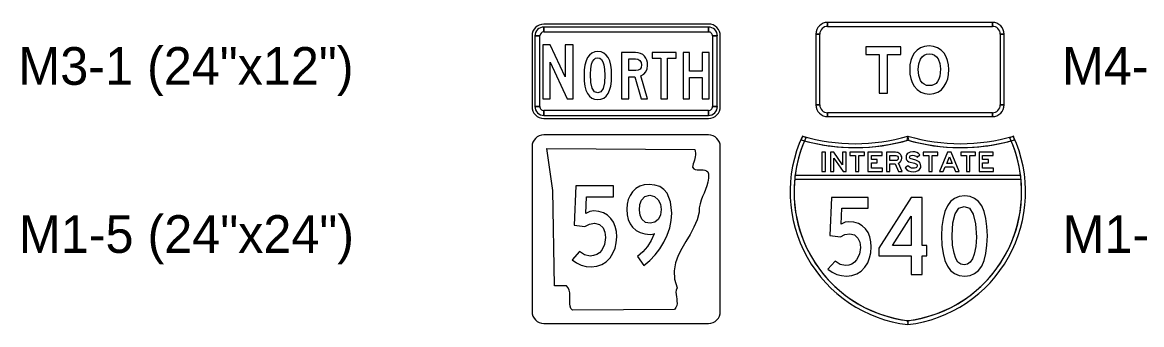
# Model space of a CAD drawing. Extents: x 620856.8 to 620948.6, y 415598.8 to 415658.2.
# Drawn here: x 620875.52 to 620887.41, y 415642.91 to 415646.11 of the extents above; entities that cross this region are included whole.
import ezdxf

# ---------------------------------------------------------------- set-up
doc = ezdxf.new("R2010")
doc.units = 0
doc.layers.add('SIGNS', color=7, linetype='Continuous')

msp = doc.modelspace()

# ---------------------------------------------------------------- linework, layer by layer
at = {"layer": 'SIGNS'}
for p, q in [((620882.81, 415646.094), (620881.06, 415646.094)), ((620881.06, 415646.011), (620881.06, 415646.063)), ((620882.81, 415646.063), (620882.81, 415646.011)), ((620885.825, 415646.112), (620884.075, 415646.112)), ((620884.075, 415646.07), (620884.075, 415646.112)), ((620885.825, 415646.112), (620885.825, 415646.07)), ((620880.935, 415645.969), (620880.935, 415645.219)), ((620880.966, 415645.969), (620881.018, 415645.969)), ((620882.851, 415645.969), (620882.903, 415645.969)), ((620882.935, 415645.219), (620882.935, 415645.969)), ((620883.95, 415645.987), (620883.95, 415645.237)), ((620883.95, 415645.987), (620883.991, 415645.987)), ((620885.908, 415645.987), (620885.95, 415645.987)), ((620885.95, 415645.237), (620885.95, 415645.987)), ((620884.852, 415645.852), (620884.481, 415645.852)), ((620884.481, 415645.852), (620884.481, 415645.77)), ((620884.852, 415645.77), (620884.852, 415645.852)), ((620884.481, 415645.77), (620884.622, 415645.77)), ((620884.622, 415645.77), (620884.622, 415645.362)), ((620884.709, 415645.362), (620884.709, 415645.77)), ((620884.709, 415645.77), (620884.852, 415645.77)), ((620884.622, 415645.362), (620884.709, 415645.362)), ((620881.018, 415645.219), (620880.966, 415645.219)), ((620882.903, 415645.219), (620882.851, 415645.219)), ((620883.991, 415645.237), (620883.95, 415645.237)), ((620885.95, 415645.237), (620885.908, 415645.237)), ((620881.06, 415645.125), (620881.06, 415645.177)), ((620882.81, 415645.177), (620882.81, 415645.125)), ((620884.075, 415645.112), (620884.075, 415645.154)), ((620884.075, 415645.112), (620885.825, 415645.112)), ((620885.825, 415645.154), (620885.825, 415645.112)), ((620881.06, 415645.094), (620882.81, 415645.094)), ((620882.81, 415644.918), (620881.06, 415644.918)), ((620883.807, 415644.905), (620883.795, 415644.865)), ((620883.845, 415644.888), (620883.807, 415644.905)), ((620884.927, 415644.905), (620884.915, 415644.865)), ((620884.938, 415644.865), (620884.927, 415644.905)), ((620886.047, 415644.905), (620886.009, 415644.888)), ((620886.058, 415644.865), (620886.047, 415644.905)), ((620880.935, 415644.793), (620880.935, 415643.043)), ((620882.935, 415643.043), (620882.935, 415644.793)), ((620883.725, 415644.447), (620886.128, 415644.447)), ((620886.124, 415644.489), (620883.73, 415644.489)), ((620880.935, 415643.043), (620880.935, 415643.043)), ((620881.06, 415642.918), (620882.81, 415642.918)), ((620884.922, 415642.947), (620884.927, 415642.905)), ((620884.927, 415642.905), (620884.932, 415642.947))]:
    msp.add_line(p, q, dxfattribs=at)
for points in [[(620882.81, 415646.063), (620881.06, 415646.063), (620881.06, 415646.011), (620882.81, 415646.011), (620882.81, 415646.063), (620882.81, 415646.063)], [(620885.825, 415646.112), (620884.075, 415646.112), (620884.075, 415646.07), (620885.825, 415646.07), (620885.825, 415646.112), (620885.825, 415646.112)], [(620880.966, 415645.969), (620880.966, 415645.219), (620881.018, 415645.219), (620881.018, 415645.969), (620880.966, 415645.969), (620880.966, 415645.969)], [(620882.903, 415645.219), (620882.903, 415645.969), (620882.851, 415645.969), (620882.851, 415645.219), (620882.903, 415645.219), (620882.903, 415645.219)], [(620883.95, 415645.987), (620883.95, 415645.237), (620883.991, 415645.237), (620883.991, 415645.987), (620883.95, 415645.987), (620883.95, 415645.987)], [(620885.95, 415645.237), (620885.95, 415645.987), (620885.908, 415645.987), (620885.908, 415645.237), (620885.95, 415645.237), (620885.95, 415645.237)], [(620881.05, 415645.302), (620881.129, 415645.302), (620881.129, 415645.689), (620881.309, 415645.302), (620881.373, 415645.302), (620881.373, 415645.874), (620881.286, 415645.874), (620881.286, 415645.533), (620881.129, 415645.874), (620881.05, 415645.874)], [(620884.622, 415645.362), (620884.709, 415645.362), (620884.709, 415645.77), (620884.852, 415645.77), (620884.852, 415645.852), (620884.481, 415645.852), (620884.481, 415645.77), (620884.622, 415645.77)], [(620882.302, 415645.302), (620882.373, 415645.302), (620882.373, 415645.731), (620882.465, 415645.731), (620882.465, 415645.793), (620882.212, 415645.793), (620882.212, 415645.731), (620882.302, 415645.731)], [(620882.539, 415645.302), (620882.607, 415645.302), (620882.607, 415645.527), (620882.741, 415645.527), (620882.741, 415645.302), (620882.816, 415645.302), (620882.816, 415645.793), (620882.741, 415645.793), (620882.741, 415645.596), (620882.607, 415645.596), (620882.607, 415645.793), (620882.539, 415645.793)], [(620881.06, 415645.125), (620882.81, 415645.125), (620882.81, 415645.177), (620881.06, 415645.177), (620881.06, 415645.125), (620881.06, 415645.125)], [(620884.075, 415645.112), (620885.825, 415645.112), (620885.825, 415645.154), (620884.075, 415645.154), (620884.075, 415645.112), (620884.075, 415645.112)], [(620882.665, 415644.764), (620882.669, 415644.745), (620882.671, 415644.725), (620882.67, 415644.706), (620882.668, 415644.687), (620882.664, 415644.668), (620882.659, 415644.649), (620882.654, 415644.63), (620882.648, 415644.612), (620882.643, 415644.594), (620882.638, 415644.575), (620882.652, 415644.559), (620882.669, 415644.55), (620882.689, 415644.546), (620882.71, 415644.546), (620882.731, 415644.546), (620882.752, 415644.547), (620882.771, 415644.544), (620882.788, 415644.538), (620882.801, 415644.526), (620882.809, 415644.506), (620882.81, 415644.46), (620882.804, 415644.418), (620882.793, 415644.377), (620882.779, 415644.339), (620882.763, 415644.301), (620882.747, 415644.263), (620882.732, 415644.224), (620882.72, 415644.185), (620882.712, 415644.143), (620882.71, 415644.099), (620882.688, 415644.017), (620882.654, 415643.939), (620882.613, 415643.863), (620882.569, 415643.788), (620882.526, 415643.714), (620882.488, 415643.638), (620882.46, 415643.559), (620882.446, 415643.477), (620882.449, 415643.389), (620882.475, 415643.296), (620882.467, 415643.272), (620882.464, 415643.249), (620882.465, 415643.225), (620882.468, 415643.2), (620882.472, 415643.177), (620882.474, 415643.153), (620882.475, 415643.13), (620882.472, 415643.108), (620882.463, 415643.087), (620882.448, 415643.067), (620881.364, 415643.057), (620881.349, 415643.077), (620881.341, 415643.101), (620881.337, 415643.127), (620881.337, 415643.156), (620881.338, 415643.185), (620881.338, 415643.215), (620881.336, 415643.244), (620881.33, 415643.271), (620881.319, 415643.295), (620881.301, 415643.315), (620881.175, 415643.315), (620881.157, 415644.327), (620881.093, 415644.774), (620882.665, 415644.764), (620882.665, 415644.764)], [(620884.014, 415644.53), (620884.051, 415644.53), (620884.051, 415644.735), (620884.014, 415644.735)], [(620884.106, 415644.53), (620884.142, 415644.53), (620884.142, 415644.672), (620884.239, 415644.53), (620884.271, 415644.53), (620884.271, 415644.735), (620884.234, 415644.735), (620884.234, 415644.601), (620884.141, 415644.735), (620884.106, 415644.735)], [(620884.369, 415644.53), (620884.405, 415644.53), (620884.405, 415644.7), (620884.465, 415644.7), (620884.465, 415644.735), (620884.31, 415644.735), (620884.31, 415644.7), (620884.369, 415644.7)], [(620884.502, 415644.53), (620884.656, 415644.53), (620884.656, 415644.566), (620884.539, 415644.566), (620884.539, 415644.622), (620884.601, 415644.622), (620884.601, 415644.658), (620884.539, 415644.658), (620884.539, 415644.698), (620884.653, 415644.698), (620884.653, 415644.735), (620884.502, 415644.735)], [(620884.898, 415644.567), (620884.915, 415644.549), (620884.935, 415644.536), (620884.958, 415644.529), (620884.983, 415644.526), (620885.012, 415644.53), (620885.037, 415644.541), (620885.049, 415644.551), (620885.058, 415644.561), (620885.063, 415644.574), (620885.064, 415644.587), (620885.062, 415644.605), (620885.057, 415644.62), (620885.047, 415644.632), (620885.033, 415644.641), (620885.013, 415644.649), (620884.975, 415644.659), (620884.961, 415644.663), (620884.951, 415644.668), (620884.946, 415644.674), (620884.944, 415644.681), (620884.946, 415644.69), (620884.952, 415644.697), (620884.963, 415644.701), (620884.978, 415644.702), (620884.992, 415644.701), (620885.005, 415644.697), (620885.017, 415644.691), (620885.027, 415644.682), (620885.055, 415644.707), (620885.039, 415644.721), (620885.021, 415644.73), (620885.001, 415644.737), (620884.979, 415644.739), (620884.952, 415644.735), (620884.93, 415644.725), (620884.92, 415644.716), (620884.912, 415644.706), (620884.908, 415644.695), (620884.907, 415644.681), (620884.909, 415644.666), (620884.914, 415644.653), (620884.924, 415644.643), (620884.938, 415644.634), (620884.996, 415644.617), (620885.01, 415644.612), (620885.019, 415644.606), (620885.025, 415644.6), (620885.027, 415644.592), (620885.026, 415644.585), (620885.023, 415644.579), (620885.018, 415644.574), (620885.011, 415644.57), (620884.997, 415644.566), (620884.982, 415644.564), (620884.966, 415644.566), (620884.952, 415644.571), (620884.939, 415644.579), (620884.927, 415644.591)], [(620885.148, 415644.53), (620885.184, 415644.53), (620885.184, 415644.7), (620885.244, 415644.7), (620885.244, 415644.735), (620885.089, 415644.735), (620885.089, 415644.7), (620885.148, 415644.7)], [(620885.55, 415644.53), (620885.586, 415644.53), (620885.586, 415644.7), (620885.646, 415644.7), (620885.646, 415644.735), (620885.491, 415644.735), (620885.491, 415644.7), (620885.55, 415644.7)], [(620885.683, 415644.53), (620885.837, 415644.53), (620885.837, 415644.566), (620885.72, 415644.566), (620885.72, 415644.622), (620885.782, 415644.622), (620885.782, 415644.658), (620885.72, 415644.658), (620885.72, 415644.698), (620885.834, 415644.698), (620885.834, 415644.735), (620885.683, 415644.735)], [(620883.725, 415644.447), (620886.128, 415644.447), (620886.128, 415644.489), (620883.725, 415644.489), (620883.725, 415644.447), (620883.725, 415644.447)], [(620881.36, 415643.592), (620881.407, 415643.559), (620881.457, 415643.536), (620881.509, 415643.522), (620881.564, 415643.518), (620881.623, 415643.524), (620881.677, 415643.542), (620881.723, 415643.572), (620881.764, 415643.615), (620881.795, 415643.663), (620881.817, 415643.715), (620881.83, 415643.773), (620881.835, 415643.836), (620881.831, 415643.893), (620881.819, 415643.945), (620881.8, 415643.992), (620881.773, 415644.032), (620881.736, 415644.067), (620881.694, 415644.092), (620881.645, 415644.107), (620881.59, 415644.112), (620881.549, 415644.105), (620881.506, 415644.085), (620881.515, 415644.26), (620881.802, 415644.26), (620881.802, 415644.376), (620881.401, 415644.376), (620881.381, 415643.96), (620881.497, 415643.945), (620881.546, 415643.971), (620881.599, 415643.98), (620881.651, 415643.968), (620881.689, 415643.933), (620881.709, 415643.887), (620881.715, 415643.83), (620881.705, 415643.755), (620881.675, 415643.694), (620881.651, 415643.667), (620881.622, 415643.648), (620881.589, 415643.637), (620881.551, 415643.633), (620881.494, 415643.645), (620881.44, 415643.68)], [(620884.077, 415643.493), (620884.123, 415643.461), (620884.171, 415643.438), (620884.222, 415643.425), (620884.275, 415643.42), (620884.333, 415643.426), (620884.384, 415643.444), (620884.43, 415643.473), (620884.47, 415643.515), (620884.5, 415643.561), (620884.521, 415643.612), (620884.534, 415643.668), (620884.538, 415643.729), (620884.534, 415643.785), (620884.523, 415643.836), (620884.504, 415643.881), (620884.478, 415643.92), (620884.442, 415643.954), (620884.401, 415643.978), (620884.354, 415643.992), (620884.301, 415643.997), (620884.261, 415643.991), (620884.218, 415643.971), (620884.227, 415644.142), (620884.506, 415644.142), (620884.506, 415644.254), (620884.117, 415644.254), (620884.097, 415643.85), (620884.21, 415643.835), (620884.258, 415643.861), (620884.309, 415643.869), (620884.36, 415643.858), (620884.396, 415643.824), (620884.415, 415643.779), (620884.422, 415643.724), (620884.412, 415643.651), (620884.383, 415643.592), (620884.359, 415643.566), (620884.331, 415643.547), (620884.299, 415643.536), (620884.263, 415643.533), (620884.207, 415643.544), (620884.155, 415643.578)]]:
    msp.add_lwpolyline(points, close=True, dxfattribs=at)
for points in [[(620885.359, 415645.661), (620885.349, 415645.706), (620885.333, 415645.747), (620885.311, 415645.784), (620885.28, 415645.818), (620885.243, 415645.843), (620885.2, 415645.857), (620885.152, 415645.862), (620885.104, 415645.857), (620885.062, 415645.843), (620885.025, 415645.818), (620884.995, 415645.785), (620884.974, 415645.748), (620884.958, 415645.708), (620884.949, 415645.663), (620884.946, 415645.613), (620884.949, 415645.562), (620884.959, 415645.516), (620884.974, 415645.473), (620884.995, 415645.435), (620885.027, 415645.399), (620885.064, 415645.373), (620885.107, 415645.358), (620885.156, 415645.352), (620885.204, 415645.358), (620885.246, 415645.373), (620885.283, 415645.398), (620885.314, 415645.434), (620885.335, 415645.472), (620885.35, 415645.514), (620885.359, 415645.56), (620885.362, 415645.611), (620885.359, 415645.661)], [(620885.362, 415645.611), (620885.359, 415645.661), (620885.349, 415645.706), (620885.333, 415645.747), (620885.311, 415645.784), (620885.28, 415645.818), (620885.243, 415645.843), (620885.2, 415645.857), (620885.152, 415645.862), (620885.104, 415645.857), (620885.062, 415645.843), (620885.025, 415645.818), (620884.995, 415645.785), (620884.974, 415645.748), (620884.958, 415645.708), (620884.949, 415645.663), (620884.946, 415645.613), (620884.949, 415645.562), (620884.959, 415645.516), (620884.974, 415645.473), (620884.995, 415645.435), (620885.027, 415645.399), (620885.064, 415645.373), (620885.107, 415645.358), (620885.156, 415645.352), (620885.204, 415645.358), (620885.246, 415645.373), (620885.283, 415645.398), (620885.314, 415645.434), (620885.335, 415645.472), (620885.35, 415645.514), (620885.359, 415645.56), (620885.362, 415645.611)], [(620881.78, 415645.548), (620881.778, 415645.608), (620881.771, 415645.659), (620881.76, 415645.703), (620881.744, 415645.739), (620881.723, 415645.766), (620881.698, 415645.786), (620881.669, 415645.798), (620881.635, 415645.802), (620881.601, 415645.798), (620881.571, 415645.786), (620881.545, 415645.766), (620881.525, 415645.739), (620881.509, 415645.703), (620881.497, 415645.659), (620881.49, 415645.608), (620881.488, 415645.548), (620881.49, 415645.488), (620881.497, 415645.436), (620881.508, 415645.392), (620881.524, 415645.357), (620881.544, 415645.328), (620881.569, 415645.309), (620881.598, 415645.297), (620881.632, 415645.293), (620881.667, 415645.297), (620881.697, 415645.309), (620881.722, 415645.328), (620881.743, 415645.357), (620881.759, 415645.392), (620881.771, 415645.436), (620881.778, 415645.488), (620881.78, 415645.548)], [(620881.709, 415645.551), (620881.705, 415645.469), (620881.69, 415645.411), (620881.666, 415645.376), (620881.633, 415645.364), (620881.599, 415645.376), (620881.575, 415645.414), (620881.56, 415645.476), (620881.556, 415645.563), (620881.559, 415645.621), (620881.568, 415645.669), (620881.579, 415645.698), (620881.594, 415645.72), (620881.611, 415645.732), (620881.633, 415645.736), (620881.654, 415645.732), (620881.672, 415645.718), (620881.686, 415645.695), (620881.698, 415645.662), (620881.706, 415645.611), (620881.709, 415645.551)], [(620881.886, 415645.302), (620881.963, 415645.302), (620881.963, 415645.536), (620882.028, 415645.536), (620882.093, 415645.302), (620882.163, 415645.302), (620882.092, 415645.544), (620882.122, 415645.561), (620882.145, 415645.588), (620882.158, 415645.62), (620882.163, 415645.655), (620882.161, 415645.685), (620882.155, 415645.711), (620882.144, 415645.734), (620882.13, 415645.754), (620882.111, 415645.771), (620882.088, 415645.783), (620882.062, 415645.79), (620882.033, 415645.793), (620881.886, 415645.793), (620881.886, 415645.302)], [(620881.963, 415645.6), (620881.963, 415645.725), (620882.035, 415645.725), (620882.06, 415645.721), (620882.08, 415645.708), (620882.093, 415645.688), (620882.098, 415645.663), (620882.094, 415645.635), (620882.082, 415645.616), (620882.064, 415645.604), (620882.037, 415645.6), (620881.963, 415645.6)], [(620885.273, 415645.618), (620885.271, 415645.576), (620885.265, 415645.54), (620885.256, 415645.51), (620885.243, 415645.485), (620885.227, 415645.465), (620885.207, 415645.452), (620885.183, 415645.443), (620885.156, 415645.441), (620885.125, 415645.444), (620885.099, 415645.455), (620885.078, 415645.472), (620885.06, 415645.497), (620885.042, 415645.548), (620885.035, 415645.611), (620885.042, 415645.673), (620885.061, 415645.723), (620885.078, 415645.747), (620885.1, 415645.764), (620885.126, 415645.774), (620885.156, 415645.777), (620885.184, 415645.774), (620885.209, 415645.764), (620885.23, 415645.748), (620885.247, 415645.725), (620885.266, 415645.677), (620885.273, 415645.618)], [(620885.273, 415645.618), (620885.271, 415645.576), (620885.265, 415645.54), (620885.256, 415645.51), (620885.243, 415645.485), (620885.227, 415645.465), (620885.207, 415645.452), (620885.183, 415645.443), (620885.156, 415645.441), (620885.125, 415645.444), (620885.099, 415645.455), (620885.078, 415645.472), (620885.06, 415645.497), (620885.042, 415645.548), (620885.035, 415645.611), (620885.042, 415645.673), (620885.061, 415645.723), (620885.078, 415645.747), (620885.1, 415645.764), (620885.126, 415645.774), (620885.156, 415645.777), (620885.184, 415645.774), (620885.209, 415645.764), (620885.23, 415645.748), (620885.247, 415645.725), (620885.266, 415645.677), (620885.273, 415645.618)], [(620881.06, 415644.918), (620881.06, 415644.918)], [(620882.81, 415644.918), (620882.81, 415644.918)], [(620880.935, 415644.793), (620880.935, 415644.793)], [(620884.7, 415644.53), (620884.736, 415644.53), (620884.736, 415644.611), (620884.793, 415644.611), (620884.828, 415644.53), (620884.866, 415644.53), (620884.829, 415644.618), (620884.843, 415644.627), (620884.853, 415644.64), (620884.86, 415644.655), (620884.862, 415644.672), (620884.861, 415644.685), (620884.857, 415644.697), (620884.851, 415644.708), (620884.842, 415644.717), (620884.832, 415644.725), (620884.821, 415644.73), (620884.808, 415644.733), (620884.795, 415644.735), (620884.7, 415644.735), (620884.7, 415644.53)], [(620884.736, 415644.646), (620884.736, 415644.698), (620884.798, 415644.698), (620884.809, 415644.697), (620884.817, 415644.691), (620884.823, 415644.683), (620884.825, 415644.672), (620884.823, 415644.662), (620884.817, 415644.654), (620884.808, 415644.648), (620884.797, 415644.646), (620884.736, 415644.646)], [(620885.262, 415644.53), (620885.302, 415644.53), (620885.323, 415644.579), (620885.412, 415644.579), (620885.432, 415644.53), (620885.472, 415644.53), (620885.386, 415644.735), (620885.349, 415644.735), (620885.262, 415644.53)], [(620885.339, 415644.616), (620885.368, 415644.685), (620885.396, 415644.616), (620885.339, 415644.616)], [(620882.055, 415643.629), (620882.124, 415643.534), (620882.186, 415643.587), (620882.242, 415643.645), (620882.292, 415643.709), (620882.335, 415643.779), (620882.371, 415643.855), (620882.398, 415643.933), (620882.413, 415644.01), (620882.419, 415644.089), (620882.406, 415644.208), (620882.369, 415644.299), (620882.334, 415644.34), (620882.291, 415644.369), (620882.24, 415644.386), (620882.181, 415644.392), (620882.127, 415644.387), (620882.079, 415644.373), (620882.037, 415644.349), (620882.003, 415644.315), (620881.976, 415644.276), (620881.958, 415644.232), (620881.947, 415644.183), (620881.943, 415644.129), (620881.947, 415644.071), (620881.958, 415644.021), (620881.977, 415643.976), (620882.004, 415643.938), (620882.04, 415643.905), (620882.083, 415643.882), (620882.133, 415643.868), (620882.189, 415643.863), (620882.213, 415643.865), (620882.237, 415643.867), (620882.234, 415643.867), (620882.201, 415643.798), (620882.16, 415643.735), (620882.111, 415643.679), (620882.055, 415643.629)], [(620882.306, 415644.126), (620882.299, 415644.069), (620882.279, 415644.024), (620882.241, 415643.991), (620882.189, 415643.98), (620882.139, 415643.99), (620882.103, 415644.023), (620882.082, 415644.066), (620882.075, 415644.121), (620882.081, 415644.179), (620882.098, 415644.226), (620882.135, 415644.264), (620882.185, 415644.277), (620882.237, 415644.265), (620882.276, 415644.23), (620882.299, 415644.182), (620882.306, 415644.126)], [(620885.771, 415643.848), (620885.767, 415643.946), (620885.756, 415644.032), (620885.737, 415644.104), (620885.711, 415644.164), (620885.677, 415644.21), (620885.636, 415644.243), (620885.587, 415644.263), (620885.531, 415644.27), (620885.473, 415644.263), (620885.423, 415644.243), (620885.381, 415644.21), (620885.346, 415644.164), (620885.319, 415644.104), (620885.3, 415644.032), (620885.289, 415643.946), (620885.285, 415643.848), (620885.289, 415643.747), (620885.3, 415643.661), (620885.319, 415643.587), (620885.346, 415643.527), (620885.381, 415643.48), (620885.423, 415643.447), (620885.473, 415643.427), (620885.531, 415643.42), (620885.587, 415643.427), (620885.636, 415643.447), (620885.677, 415643.48), (620885.711, 415643.527), (620885.737, 415643.587), (620885.756, 415643.661), (620885.767, 415643.747), (620885.771, 415643.848)], [(620884.618, 415643.636), (620884.961, 415643.636), (620884.961, 415643.436), (620885.08, 415643.436), (620885.08, 415643.636), (620885.129, 415643.636), (620885.129, 415643.745), (620885.08, 415643.745), (620885.08, 415644.254), (620884.961, 415644.254), (620884.618, 415643.718), (620884.618, 415643.636)], [(620885.654, 415643.832), (620885.648, 415643.735), (620885.632, 415643.653), (620885.613, 415643.603), (620885.589, 415643.567), (620885.559, 415643.546), (620885.524, 415643.539), (620885.489, 415643.546), (620885.459, 415643.569), (620885.435, 415643.608), (620885.417, 415643.662), (620885.402, 415643.747), (620885.397, 415643.849), (620885.405, 415643.985), (620885.429, 415644.082), (620885.468, 415644.14), (620885.524, 415644.16), (620885.58, 415644.14), (620885.621, 415644.078), (620885.645, 415643.975), (620885.654, 415643.832)], [(620884.763, 415643.745), (620884.961, 415644.055), (620884.961, 415643.745), (620884.763, 415643.745)], [(620881.06, 415642.918), (620881.06, 415642.918)], [(620882.81, 415642.918), (620882.81, 415642.918)]]:
    msp.add_lwpolyline(points, dxfattribs=at)
for centre, radius, start, end in [((620881.06, 415645.969), 0.125, 90.0002, 179.9998), ((620881.06, 415645.969), 0.0937, 90.0002, 179.9998), ((620882.81, 415645.969), 0.125, 360, 90.0002), ((620882.81, 415645.969), 0.0937, 360, 90.0002), ((620884.075, 415645.987), 0.125, 90.0002, 179.9998), ((620884.075, 415645.987), 0.125, 90.0002, 179.9998), ((620884.075, 415645.987), 0.0833, 90.0002, 179.9998), ((620885.825, 415645.987), 0.125, 360, 90.0002), ((620885.825, 415645.987), 0.125, 0, 90.0002), ((620885.825, 415645.987), 0.0833, 0, 90.0002), ((620881.06, 415645.969), 0.0417, 90.0002, 179.9998), ((620882.81, 415645.969), 0.0417, 360, 90.0002), ((620881.06, 415645.219), 0.125, 179.9998, 270.0001), ((620881.06, 415645.219), 0.0937, 179.9998, 270.0001), ((620881.06, 415645.219), 0.0417, 179.9998, 270.0001), ((620882.81, 415645.219), 0.125, 270.0001, 0.0003), ((620882.81, 415645.219), 0.0937, 270.0001, 0.0003), ((620882.81, 415645.219), 0.0417, 270.0001, 0.0003), ((620884.075, 415645.237), 0.125, 179.9998, 270.0001), ((620884.075, 415645.237), 0.125, 179.9998, 270.0001), ((620884.075, 415645.237), 0.0833, 179.9998, 270.0001), ((620885.825, 415645.237), 0.125, 270.0001, 0.0003), ((620885.825, 415645.237), 0.125, 270.0001, 0.0003), ((620885.825, 415645.237), 0.0833, 270.0001, 0.0003), ((620881.06, 415644.793), 0.125, 90.0002, 179.9998), ((620882.81, 415644.793), 0.125, 360, 90), ((620885.093, 415644.312), 1.417, 155.2469, 263.2437), ((620885.093, 415644.312), 1.417, 155.2469, 263.2437), ((620885.093, 415644.312), 1.375, 155.2469, 263.2437), ((620884.367, 415646.825), 2.042, 253.7424, 286.2577), ((620884.367, 415646.825), 2, 253.7424, 286.2577), ((620884.367, 415646.825), 2, 253.7424, 286.2577), ((620884.364, 415646.826), 2.042, 254.8528, 286.0062), ((620885.487, 415646.825), 2.042, 253.7424, 286.2577), ((620884.76, 415644.312), 1.375, 276.7564, 24.7532), ((620884.76, 415644.312), 1.417, 276.7564, 24.7532), ((620885.487, 415646.825), 2, 253.7424, 286.2577), ((620884.76, 415644.312), 1.417, 276.7564, 24.7532), ((620885.487, 415646.825), 2, 253.7424, 286.2577), ((620885.49, 415646.826), 2.042, 253.9939, 285.1473), ((620885.093, 415644.312), 1.375, 156.7269, 172.6247), ((620884.76, 415644.312), 1.375, 7.3752, 23.2733), ((620885.093, 415644.312), 1.375, 174.3597, 263.0392), ((620884.76, 415644.312), 1.375, 276.9609, 5.6399), ((620881.06, 415643.043), 0.125, 180, 270), ((620882.81, 415643.043), 0.125, 270.0001, 0.0003)]:
    msp.add_arc(centre, radius, start, end, dxfattribs=at)

# ---------------------------------------------------------------- texts
for s, p in [('M3-1 (24"x12")', (620875.479, 415645.45)), ('M4-5 (24"x12")', (620886.563, 415645.45)), ('M1-5 (24"x24")', (620875.484, 415643.666)), ('M1-1 (30"x24")', (620886.568, 415643.666))]:
    msp.add_text(s, height=0.4, rotation=0, dxfattribs=at).set_placement(p)

doc.saveas('drawing.dxf')
